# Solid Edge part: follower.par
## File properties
Author: Deepak Maini
Template: normal.par
Last saved by: MYPC
Revision: 5
Application: Solid Edge
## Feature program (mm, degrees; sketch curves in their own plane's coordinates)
sketch for "unnamed Protrusion 1" plane through (0, 0, 18.8714) normal (0, 0, 1) x-axis (1, 0, 0)
  line (-78.836, 27.8599) -> (-22.3427, 36.4287)
  arc centre (-20.5076, 24.3301) radius 12.2369 from (-22.3427, 36.4287) to (-20.5076, 12.0932) cw
  line (-77.6471, 12.0932) -> (-20.5076, 12.0932)
  arc centre (-77.6471, 20.0214) radius 7.9282 from (-77.6471, 12.0932) to (-78.836, 27.8599) cw
extrude "unnamed Protrusion 1" add finite 8.5604 along +normal
sketch for "unnamed Protrusion 2" plane through (0, 0, -11.35) normal (0, 0, 1) x-axis (1, 0, 0)
  circle centre (-20.5076, 24.3301) radius 3.5
extrude "unnamed Protrusion 2" add along +normal
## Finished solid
Body 1: solid body, 8 faces, 14 edges, 8 vertices.
  Faces by surface: plane 5, cylinder 3
  Edges by curve: line 8, circle 6
Bounding box of the edges (mm): 77.305 x 24.474 x 38.782, from (-85.5752, 12.0932, -11.35) to (-8.2707, 36.567, 27.4319).
Cylindrical faces by radius (mm): R3.5 x1, R7.9282 x1, R12.2369 x1
Planar faces by outward normal: +z 1, -y 1, -z 2, oblique 1
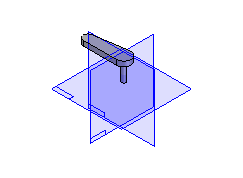
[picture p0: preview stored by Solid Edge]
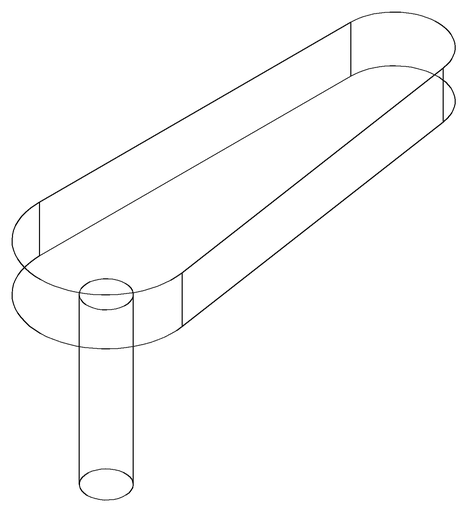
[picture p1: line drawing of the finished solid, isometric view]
